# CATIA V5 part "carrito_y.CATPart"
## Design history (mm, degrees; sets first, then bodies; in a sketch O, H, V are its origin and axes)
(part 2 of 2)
    midpoint: P2 L1
    vertical: L5 V, L7 V
    concentricity: A2 E1
    symmetry: P2 P14 H, A1 A3 H, P11 P15 H, P12 P16 H, A2 A4 H, P3 P17 H, P4 P18 H, P5 P19 H, P6 P20 H, P7 P21 H, L5 L9 H, P8 P22 H, P9 P23 H, P10 P24 H, L1 L10 H, L2 L11 H, L3 L12 H, L4 L13 H, L6 L14 H, L7 L15 H, L8 L16 H, P2 P26 V, A1 A5 V, P11 P27 V, P12 P28 V, A2 A6 V, P3 P29 V, P4 P30 V, P5 P31 V, P6 P32 V, P7 P33 V, L5 L17 V, P8 P34 V, P9 P35 V, P10 P36 V, P14 P38 V, A3 A7 V, P15 P39 V, P16 P40 V, A4 A8 V, P17 P41 V, P18 P42 V, P19 P43 V, P20 P44 V, P21 P45 V, L9 L18 V, P22 P46 V, P23 P47 V, P24 P48 V, L1 L19 V, L2 L20 V, L3 L21 V, L4 L22 V, L6 L23 V, L7 L24 V, L8 L25 V, L10 L26 V, L11 L27 V, L12 L28 V, L13 L29 V, L14 L30 V, L15 L31 V, L16 L32 V
  Pocket7: profile Sketch9, direction (0, -1, 0), length 3
  Sketch10 on face of Pocket7, origin (0, 0, 0), H (1, 0, 0), V (0, 0, 1)
    line L1 (-5.7735, 20) -> (5.7735, 20)
    line L2 (5.7735, 20) -> (5.7735, -20)
    line L3 (5.7735, -20) -> (-5.7735, -20)
    line L4 (-5.7735, -20) -> (-5.7735, 20)
    reference projected point E1 (5.7735, 0) from edge [face of Pocket2 from Sketch4.L5 | face of Pocket2 from Sketch4.L6]
    reference projected point E2 (-5.7735, 0) from edge [face of Pocket2 from Sketch4.L2 | face of Pocket2 from Sketch4.L3]
    distance L1 L3 = 40
    distance H L1 = 20
    horizontal: L1 H, L3 H
    vertical: L2 V, L4 V
    coincidence: L2 E1, E2 L4
  Pad3: profile Sketch10, direction (0, -1, 0), length 20
  Fillet2: radius 10, on edge [face of Pad1 from Sketch1.L12 | face of Pad1 from Sketch1.L8]; edge [face of Pad1 from Sketch1.L2 | face of Pad1 from Sketch1.L3]; edge [face of Pad1 from Sketch1.L18 | face of Pad1 from Sketch1.L20]; edge [face of Pad1 from Sketch1.L15 | face of Pad1 from Sketch1.L14]
  Fillet3: radius 20, on edge [face of Pad1 from Sketch1.L35 | face of Pad1 from Sketch1.L4]; edge [face of Pad1 from Sketch1.L27 | face of Pad1 from Sketch1.L35]; edge [face of Pad1 from Sketch1.L23 | face of Pad1 from Sketch1.L38]; edge [face of Pad1 from Sketch1.L38 | face of Pad1 from Sketch1.L30]; edge [face of Pad1 from Sketch1.L9 | face of Pad1 from Sketch1.L36]; edge [face of Pad1 from Sketch1.L36 | face of Pad1 from Sketch1.L33]; edge [face of Pad1 from Sketch1.L34 | face of Pad1 from Sketch1.L37]; edge [face of Pad1 from Sketch1.L37 | face of Pad1 from Sketch1.L22]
